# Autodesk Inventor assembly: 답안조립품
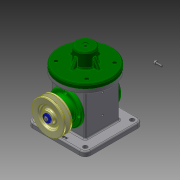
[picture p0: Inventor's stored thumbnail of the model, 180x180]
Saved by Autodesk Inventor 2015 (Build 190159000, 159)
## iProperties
Created: 2021-05
Part Number: 답안조립품
Document SubType Name: Assembly
Designer: 1019876
Author: 1019876
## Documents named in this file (19)
- C:\Users\1019876\Desktop\710506V1006 (1)\답안조립품.iam
- C:\Users\1019876\Desktop\710506V1006 (1)\E-링.ipt
- C:\Users\1019876\Desktop\710506V1006 (1)\V-벨트풀리.ipt
- C:\Users\1019876\Desktop\710506V1006 (1)\덮개.ipt
- C:\Users\1019876\Desktop\710506V1006 (1)\뒤커버.ipt
- C:\Users\1019876\Desktop\710506V1006 (1)\링크.ipt
- C:\Users\1019876\Desktop\710506V1006 (1)\베어링 17 x 40 x 12.ipt
- C:\Users\1019876\Desktop\710506V1006 (1)\본체.ipt
- C:\Users\1019876\Desktop\710506V1006 (1)\볼트 M4 x 10.ipt
- C:\Users\1019876\Desktop\710506V1006 (1)\볼트 M4 x 12.ipt
- 볼트 M4 x 12.ipt
- C:\Users\1019876\Desktop\710506V1006 (1)\슬라이더.ipt
- C:\Users\1019876\Desktop\710506V1006 (1)\앞커버.ipt
- C:\Users\1019876\Desktop\710506V1006 (1)\오일 실 17 30 8.ipt
- C:\Users\1019876\Desktop\710506V1006 (1)\와셔 4x16.ipt
- C:\Users\1019876\Desktop\710506V1006 (1)\클레비스 핀 6 x 22.ipt
- 클레비스 핀 6 x 22.ipt
- C:\Users\1019876\Desktop\710506V1006 (1)\키 4 x 4 x 12.ipt
- C:\Users\1019876\Desktop\710506V1006 (1)\편심축.ipt
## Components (2 placed, 2 different names)
1. E-링:1
2. V-벨트풀리:1
